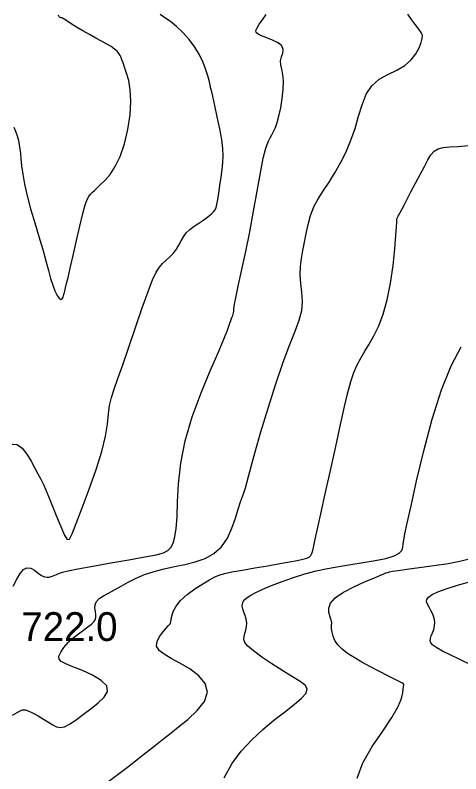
# Model space of a CAD drawing. Extents: x 2566142 to 2571431, y 418755 to 421584.
# Drawn here: x 2570258.6 to 2570491.1, y 419106 to 419501.7 of the extents above; entities that cross this region are included whole.
import ezdxf

# ---------------------------------------------------------------- set-up
doc = ezdxf.new("R2010")
doc.units = 0
for name, color, linetype in [('Contour_ADS_Major', 7, 'Continuous'), ('Contour_ADS_Minor', 7, 'Continuous'), ('Contour_ADS_Spot_Elevation', 7, 'Continuous')]:
    doc.layers.add(name, color=color, linetype=linetype)

msp = doc.modelspace()

# ---------------------------------------------------------------- linework, layer by layer
at = {"layer": 'Contour_ADS_Major'}
for points in [[(2570282.35, 419169.48), (2570284.05, 419171.89), (2570286.31, 419174.44), (2570288.88, 419176.9), (2570291.56, 419179.09), (2570294.16, 419180.99), (2570296.49, 419182.63), (2570298.36, 419184.04), (2570299.64, 419185.25), (2570300.38, 419186.39), (2570300.69, 419187.57), (2570300.66, 419188.95), (2570300.41, 419190.59), (2570300.21, 419192.4), (2570300.3, 419194.24), (2570300.98, 419195.95), (2570302.44, 419197.45), (2570304.6, 419198.83), (2570307.32, 419200.26), (2570310.44, 419201.91), (2570313.85, 419203.86), (2570317.57, 419205.99), (2570321.65, 419208.11), (2570326.13, 419210.02), (2570331.05, 419211.58), (2570336.29, 419212.88), (2570341.72, 419214.06), (2570347.19, 419215.24), (2570352.57, 419216.6), (2570357.66, 419218.39), (2570362.27, 419220.87), (2570366.2, 419224.34), (2570369.31, 419228.91), (2570371.69, 419234.14), (2570373.53, 419239.41), (2570374.97, 419244.12), (2570376.15, 419247.82), (2570377.15, 419250.68), (2570377.99, 419253.05), (2570378.71, 419255.26), (2570379.39, 419257.71), (2570380.28, 419261.12), (2570381.65, 419266.25), (2570383.78, 419273.88), (2570386.84, 419284.43), (2570390.57, 419296.76), (2570394.57, 419309.39), (2570398.46, 419320.81), (2570401.91, 419329.9), (2570404.74, 419336.94), (2570406.84, 419342.62), (2570408.09, 419347.6), (2570408.43, 419352.43), (2570408.17, 419357.19), (2570407.69, 419361.82), (2570407.37, 419366.3), (2570407.49, 419370.6), (2570407.99, 419374.81), (2570408.74, 419379.03), (2570409.6, 419383.37), (2570410.46, 419387.91), (2570411.44, 419392.56), (2570412.71, 419397.2), (2570414.42, 419401.7), (2570416.69, 419406), (2570419.4, 419410.25), (2570422.37, 419414.66), (2570425.43, 419419.42), (2570428.41, 419424.69), (2570431.23, 419430.41), (2570433.77, 419436.45), (2570435.96, 419442.7), (2570437.79, 419449), (2570439.57, 419455.03), (2570441.7, 419460.47), (2570444.61, 419464.96), (2570448.52, 419468.29), (2570453.06, 419470.83), (2570457.69, 419473.06), (2570461.88, 419475.46), (2570465.19, 419478.38), (2570467.64, 419481.61), (2570469.36, 419484.77), (2570470.46, 419487.49), (2570471.03, 419489.55), (2570471.06, 419491.16), (2570470.49, 419492.68), (2570469.27, 419494.47), (2570467.42, 419496.78), (2570465.35, 419499.45), (2570463.54, 419502.23)], [(2570257.26, 419136.56), (2570259.59, 419137.9), (2570261.22, 419138.88), (2570262.46, 419139.41), (2570263.71, 419139.43), (2570265.36, 419138.9), (2570267.7, 419137.8), (2570270.49, 419136.29), (2570273.39, 419134.59), (2570276.05, 419132.91), (2570278.23, 419131.47), (2570280.13, 419130.46), (2570282.07, 419130.1), (2570284.36, 419130.59), (2570287.23, 419132.06), (2570290.6, 419134.32), (2570294.3, 419137.08), (2570298.17, 419140.07), (2570301.96, 419143.06), (2570305.06, 419146.02), (2570306.77, 419148.94), (2570306.39, 419151.84), (2570303.52, 419154.71), (2570298.91, 419157.43), (2570293.63, 419159.85), (2570288.71, 419161.86), (2570285.02, 419163.38), (2570282.65, 419164.62), (2570281.48, 419165.88), (2570281.43, 419167.43), (2570282.35, 419169.48)]]:
    msp.add_lwpolyline(points, dxfattribs=at)
at = {"layer": 'Contour_ADS_Minor'}
for points in [[(2570286.2, 419364.94), (2570287.31, 419369.76), (2570288.8, 419376.42), (2570290.5, 419384.11), (2570292.24, 419391.74), (2570293.81, 419398.21), (2570295.07, 419402.72), (2570296.08, 419405.55), (2570296.96, 419407.22), (2570297.81, 419408.3), (2570298.75, 419409.25), (2570299.89, 419410.31), (2570301.33, 419411.61), (2570303.18, 419413.32), (2570305.5, 419415.59), (2570308.13, 419418.64), (2570310.84, 419422.71), (2570313.4, 419428.03), (2570315.63, 419434.68), (2570317.38, 419442.13), (2570318.54, 419449.73), (2570318.98, 419456.79), (2570318.67, 419462.78), (2570317.82, 419467.66), (2570316.72, 419471.56), (2570315.67, 419474.56), (2570314.89, 419476.79), (2570314.32, 419478.43), (2570313.84, 419479.69), (2570313.32, 419480.76), (2570312.66, 419481.82), (2570311.74, 419482.92), (2570310.45, 419484.08), (2570308.7, 419485.32), (2570306.41, 419486.67), (2570303.67, 419488.14), (2570300.59, 419489.77), (2570297.29, 419491.57), (2570293.9, 419493.53), (2570290.65, 419495.5), (2570287.78, 419497.29), (2570285.54, 419498.7), (2570284.09, 419499.6), (2570283.27, 419500.09), (2570282.86, 419500.3), (2570282.61, 419500.37), (2570282.34, 419500.43), (2570282.04, 419500.52), (2570281.75, 419500.67), (2570281.51, 419500.91), (2570281.34, 419501.26), (2570281.16, 419501.82)], [(2570352.28, 419485.05), (2570349.32, 419489.03), (2570346.11, 419492.71), (2570342.81, 419495.88), (2570339.61, 419498.42), (2570336.69, 419500.41), (2570334.24, 419502)], [(2570397.12, 419453.41), (2570397.93, 419458.21), (2570398.47, 419463.02), (2570398.6, 419467.35), (2570398.27, 419470.83), (2570397.69, 419473.59), (2570397.2, 419475.87), (2570397.09, 419477.93), (2570397.55, 419479.96), (2570398.17, 419481.96), (2570398.41, 419483.89), (2570397.72, 419485.67), (2570395.75, 419487.28), (2570392.92, 419488.69), (2570389.85, 419489.91), (2570387.14, 419490.94), (2570385.3, 419491.79), (2570384.34, 419492.64), (2570384.2, 419493.67), (2570384.77, 419495.08), (2570385.96, 419497.01), (2570387.61, 419499.38), (2570389.52, 419502.07)], [(2570257.08, 419278.03), (2570259.61, 419277.82), (2570262.14, 419275.89), (2570264.59, 419272.72), (2570266.85, 419269), (2570268.83, 419265.42), (2570270.48, 419262.43), (2570271.96, 419259.65), (2570273.51, 419256.49), (2570275.34, 419252.34), (2570277.59, 419246.85), (2570280.05, 419240.74), (2570282.41, 419234.98), (2570284.38, 419230.55), (2570285.78, 419228.28), (2570286.95, 419228.44), (2570288.36, 419231.18), (2570290.47, 419236.63), (2570293.57, 419244.71), (2570297.23, 419254.45), (2570300.85, 419264.67), (2570303.8, 419274.19), (2570305.66, 419282.08), (2570306.67, 419288.47), (2570307.25, 419293.7), (2570307.83, 419298.17), (2570308.77, 419302.28), (2570310.18, 419306.7), (2570312.14, 419312.13), (2570314.72, 419319.28), (2570317.9, 419328.51), (2570321.4, 419338.86), (2570324.85, 419348.99), (2570327.91, 419357.61), (2570330.3, 419363.72), (2570332.19, 419367.71), (2570333.82, 419370.28), (2570335.47, 419372.16), (2570337.31, 419373.94), (2570339.25, 419375.76), (2570341.13, 419377.65), (2570342.76, 419379.65), (2570344.06, 419381.77), (2570345.19, 419383.94), (2570346.38, 419386.08), (2570347.86, 419388.12), (2570349.79, 419389.98), (2570352.03, 419391.69), (2570354.35, 419393.24), (2570356.54, 419394.65), (2570358.42, 419395.95), (2570359.96, 419397.15), (2570361.2, 419398.24), (2570362.16, 419399.24), (2570362.86, 419400.21), (2570363.39, 419401.39), (2570363.84, 419403.06), (2570364.29, 419405.51), (2570364.83, 419408.91), (2570365.42, 419412.95), (2570366, 419417.22), (2570366.51, 419421.29), (2570366.9, 419424.89), (2570367.07, 419428.36), (2570366.93, 419432.16), (2570366.37, 419436.8), (2570365.36, 419442.53), (2570364.07, 419448.75), (2570362.76, 419454.65), (2570361.66, 419459.43), (2570360.96, 419462.47), (2570360.59, 419464.06), (2570360.45, 419464.68), (2570360.43, 419464.83), (2570360.41, 419464.95), (2570360.33, 419465.31), (2570360.13, 419466.15), (2570359.75, 419467.71), (2570359.11, 419470.13), (2570358.13, 419473.3), (2570356.72, 419476.98), (2570354.79, 419480.97), (2570352.28, 419485.05)], [(2570257.49, 419203.86), (2570259.43, 419207.47), (2570261.21, 419210.44), (2570262.94, 419212.53), (2570264.73, 419213.5), (2570266.67, 419213.25), (2570268.67, 419212.16), (2570270.62, 419210.72), (2570272.39, 419209.45), (2570273.92, 419208.73), (2570275.21, 419208.52), (2570276.35, 419208.65), (2570277.37, 419208.95), (2570278.34, 419209.28), (2570279.26, 419209.63), (2570280.1, 419209.98), (2570280.88, 419210.34), (2570281.7, 419210.72), (2570283.2, 419211.22), (2570286.15, 419211.93), (2570291.32, 419212.97), (2570299.1, 419214.38), (2570308.45, 419216.01), (2570317.96, 419217.66), (2570326.19, 419219.12), (2570332.08, 419220.27), (2570335.9, 419221.29), (2570338.27, 419222.45), (2570339.79, 419224.03), (2570340.99, 419226.29), (2570341.96, 419229.53), (2570342.67, 419234.02), (2570343.12, 419240.06), (2570343.37, 419247.86), (2570343.83, 419257.24), (2570344.97, 419267.96), (2570347.27, 419279.75), (2570351.02, 419292.27), (2570355.65, 419304.7), (2570360.41, 419316.14), (2570364.55, 419325.68), (2570367.47, 419332.66), (2570369.34, 419337.4), (2570370.45, 419340.5), (2570371.15, 419342.51), (2570371.68, 419343.96), (2570372.1, 419345.03), (2570372.4, 419345.85), (2570372.57, 419346.54), (2570372.64, 419347.3), (2570372.76, 419348.61), (2570373.11, 419351.02), (2570373.88, 419355.09), (2570375.2, 419361.21), (2570376.94, 419369.12), (2570378.93, 419378.42), (2570381, 419388.68), (2570382.98, 419399.44), (2570384.84, 419409.96), (2570386.55, 419419.44), (2570388.06, 419427.08), (2570389.38, 419432.35), (2570390.53, 419435.68), (2570391.56, 419437.78), (2570392.52, 419439.35), (2570393.45, 419441.01), (2570394.36, 419443.06), (2570395.28, 419445.69), (2570396.2, 419449.11), (2570397.12, 419453.41)], [(2570257.88, 419443.26), (2570258.78, 419441.27), (2570259.59, 419438.8), (2570260.25, 419436.28), (2570260.73, 419434.03), (2570261.06, 419431.88), (2570261.33, 419429.54), (2570261.6, 419426.71), (2570261.96, 419423.15), (2570262.52, 419418.78), (2570263.42, 419413.59), (2570264.76, 419407.54), (2570266.6, 419400.7), (2570268.76, 419393.43), (2570270.98, 419386.2), (2570273, 419379.48), (2570274.63, 419373.62), (2570275.94, 419368.63), (2570277.07, 419364.4), (2570278.16, 419360.84), (2570279.29, 419357.88), (2570280.43, 419355.59), (2570281.49, 419354.07), (2570282.4, 419353.41), (2570283.09, 419353.68), (2570283.61, 419354.66), (2570284.03, 419356.1), (2570284.42, 419357.75), (2570284.85, 419359.47), (2570285.41, 419361.69), (2570286.2, 419364.94)], [(2570333.96, 419177.7), (2570335.74, 419180.12), (2570337.42, 419182.05), (2570338.54, 419183.29), (2570339.15, 419183.95), (2570339.41, 419184.22), (2570339.49, 419184.3), (2570339.54, 419184.39), (2570339.6, 419184.65), (2570339.73, 419185.28), (2570339.95, 419186.45), (2570340.33, 419188.29), (2570341.1, 419190.68), (2570342.54, 419193.46), (2570344.9, 419196.47), (2570348.31, 419199.54), (2570352.34, 419202.48), (2570356.44, 419205.1), (2570360.02, 419207.21), (2570362.73, 419208.69), (2570365.1, 419209.7), (2570367.85, 419210.48), (2570371.7, 419211.28), (2570377.13, 419212.27), (2570383.62, 419213.41), (2570390.37, 419214.57), (2570396.62, 419215.64), (2570401.73, 419216.55), (2570405.69, 419217.3), (2570408.64, 419217.95), (2570410.72, 419218.54), (2570412.08, 419219.13), (2570412.93, 419219.88), (2570413.46, 419220.96), (2570413.89, 419222.54), (2570414.41, 419224.84), (2570415.18, 419228.4), (2570416.34, 419233.8), (2570418.04, 419241.62), (2570420.36, 419252.13), (2570423.05, 419264.3), (2570425.83, 419276.77), (2570428.37, 419288.2), (2570430.46, 419297.53), (2570432.18, 419304.88), (2570433.73, 419310.69), (2570435.29, 419315.36), (2570437, 419319.32), (2570438.9, 419322.88), (2570440.99, 419326.39), (2570443.28, 419330.15), (2570445.75, 419334.47), (2570448.26, 419339.6), (2570450.65, 419345.78), (2570452.76, 419353.24), (2570454.47, 419362), (2570455.76, 419371.21), (2570456.69, 419379.82), (2570457.28, 419386.78), (2570457.59, 419391.31), (2570457.7, 419393.8), (2570457.71, 419394.95), (2570457.75, 419395.42), (2570457.89, 419395.8), (2570458.14, 419396.26), (2570458.5, 419396.87), (2570458.97, 419397.7), (2570459.56, 419398.83), (2570460.36, 419400.42), (2570461.49, 419402.65), (2570463.06, 419405.69), (2570465.13, 419409.62), (2570467.49, 419414.08), (2570469.91, 419418.62), (2570472.1, 419422.79), (2570473.92, 419426.2), (2570475.53, 419428.83), (2570477.23, 419430.75), (2570479.28, 419432), (2570481.93, 419432.69), (2570485.35, 419433.04), (2570489.66, 419433.3), (2570494.99, 419433.73)], [(2570411.01, 419150.29), (2570409.93, 419152.17), (2570407.3, 419154.15), (2570403.3, 419156.6), (2570398.18, 419159.76), (2570392.58, 419163.34), (2570387.23, 419166.93), (2570382.86, 419170.11), (2570380.01, 419172.58), (2570378.5, 419174.48), (2570377.98, 419176.05), (2570378.09, 419177.55), (2570378.49, 419179.18), (2570378.97, 419180.94), (2570379.35, 419182.8), (2570379.45, 419184.72), (2570379.14, 419186.67), (2570378.55, 419188.57), (2570377.88, 419190.37), (2570377.33, 419192), (2570377.06, 419193.42), (2570377.13, 419194.67), (2570377.56, 419195.81), (2570378.38, 419196.91), (2570379.64, 419198.02), (2570381.5, 419199.23), (2570384.13, 419200.61), (2570387.73, 419202.26), (2570392.38, 419204.21), (2570397.83, 419206.32), (2570403.75, 419208.41), (2570409.8, 419210.29), (2570415.72, 419211.82), (2570421.59, 419213.07), (2570427.54, 419214.15), (2570433.73, 419215.14), (2570440.16, 419216.15), (2570446.43, 419217.21), (2570451.99, 419218.36), (2570456.29, 419219.62), (2570458.97, 419221.01), (2570460.34, 419222.54), (2570460.88, 419224.18), (2570461.07, 419225.93), (2570461.35, 419227.96), (2570461.98, 419231.19), (2570463.17, 419236.75), (2570465.15, 419245.75), (2570468.07, 419258.79), (2570471.81, 419274.48), (2570476.18, 419290.93), (2570481.02, 419306.21), (2570486.13, 419318.8), (2570491.3, 419328.68)], [(2570453.86, 419211.33), (2570455.51, 419211.66), (2570458.36, 419212.12), (2570462.91, 419212.75), (2570469.41, 419213.59), (2570476.98, 419214.6), (2570484.45, 419215.72), (2570490.64, 419216.86), (2570494.73, 419217.99)], [(2570436.98, 419103.77), (2570439.97, 419111.78), (2570444.86, 419120.18), (2570450.36, 419128.28), (2570455.19, 419135.41), (2570458.37, 419141.03), (2570460.09, 419145.23), (2570460.84, 419148.22), (2570461.09, 419150.24), (2570461.25, 419151.52), (2570461.37, 419152.24), (2570461.41, 419152.6), (2570461.33, 419152.79), (2570461.05, 419153), (2570460.35, 419153.38), (2570458.94, 419154.1), (2570456.55, 419155.31), (2570453.02, 419157.11), (2570448.7, 419159.34), (2570444.03, 419161.8), (2570439.49, 419164.27), (2570435.44, 419166.6), (2570431.99, 419168.82), (2570429.17, 419171), (2570427, 419173.23), (2570425.47, 419175.55), (2570424.5, 419177.84), (2570423.95, 419179.93), (2570423.71, 419181.67), (2570423.66, 419182.95), (2570423.71, 419183.84), (2570423.78, 419184.48), (2570423.81, 419185), (2570423.72, 419185.53), (2570423.5, 419186.19), (2570423.17, 419187.11), (2570422.72, 419188.42), (2570422.26, 419190.21), (2570422.22, 419192.42), (2570423.17, 419194.96), (2570425.64, 419197.75), (2570429.94, 419200.67), (2570435.35, 419203.52), (2570440.91, 419206.08), (2570445.68, 419208.13), (2570448.92, 419209.5), (2570450.89, 419210.33), (2570452.05, 419210.79), (2570452.88, 419211.07), (2570453.86, 419211.33)], [(2570496.65, 419162.67), (2570490.65, 419165.56), (2570485.58, 419167.98), (2570481.58, 419169.98), (2570478.6, 419171.64), (2570476.59, 419173.04), (2570475.47, 419174.26), (2570475.08, 419175.42), (2570475.23, 419176.61), (2570475.73, 419177.95), (2570476.38, 419179.51), (2570477.02, 419181.27), (2570477.48, 419183.19), (2570477.58, 419185.21), (2570477.21, 419187.27), (2570476.49, 419189.31), (2570475.56, 419191.23), (2570474.59, 419192.95), (2570473.76, 419194.42), (2570473.27, 419195.7), (2570473.35, 419196.9), (2570474.21, 419198.12), (2570476.09, 419199.45), (2570479.14, 419200.92), (2570483.52, 419202.57), (2570489.42, 419204.42), (2570496.8, 419206.46)], [(2570307.38, 419102.19), (2570317.21, 419109.53), (2570325.6, 419116.13), (2570331.74, 419120.97), (2570336.2, 419124.47), (2570339.94, 419127.39), (2570343.88, 419130.51), (2570348.65, 419134.41), (2570353.48, 419138.96), (2570357.29, 419143.8), (2570358.98, 419148.61), (2570357.8, 419153.08), (2570354.38, 419157.14), (2570349.65, 419160.7), (2570344.57, 419163.73), (2570339.99, 419166.22), (2570336.26, 419168.36), (2570333.65, 419170.41), (2570332.41, 419172.6), (2570332.66, 419175.1), (2570333.96, 419177.7)], [(2570367.58, 419103.94), (2570371.65, 419111.24), (2570376.52, 419117.87), (2570381.99, 419123.79), (2570387.78, 419129.11), (2570393.61, 419133.9), (2570399.18, 419138.23), (2570404.11, 419142.09), (2570407.98, 419145.41), (2570410.39, 419148.13), (2570411.01, 419150.29)]]:
    msp.add_lwpolyline(points, dxfattribs=at)

# ---------------------------------------------------------------- texts
at = {"layer": 'Contour_ADS_Spot_Elevation'}
msp.add_text('722.0', height=15, dxfattribs=at).set_placement((2570261.81, 419175.3))

doc.saveas('drawing.dxf')
